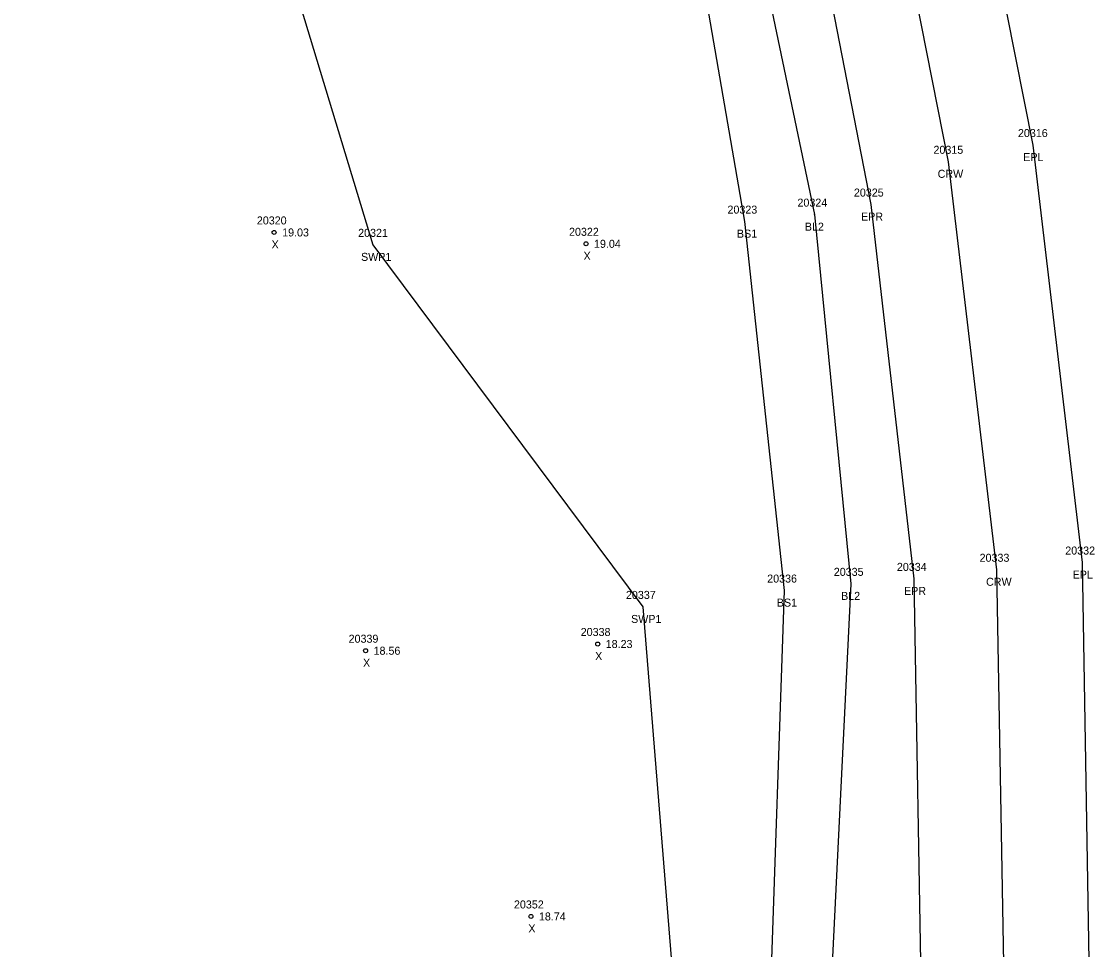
# Model space of a CAD drawing. Extents: x 2432729 to 2433340, y 684958 to 688103.
# Drawn here: x 2433033 to 2433167, y 686221.7 to 686337.6 of the extents above; entities that cross this region are included whole.
import ezdxf

# ---------------------------------------------------------------- set-up
doc = ezdxf.new("R2010")
doc.units = 0
for name, color, linetype in [('RD_DTM_BkLn1', 7, 'Continuous'), ('RD_DTM_BkLn2', 7, 'Continuous'), ('RD_EX_H2O', 7, 'Continuous'), ('RD_EX_H2O_txCode', 7, 'Continuous'), ('RD_EX_Road', 7, 'Continuous'), ('RD_EX_Road_txCode', 7, 'Continuous'), ('RD_Sketch8', 7, 'Continuous'), ('RD_SMD_Locator', 7, 'Continuous'), ('RD_SMD_Misc', 7, 'Continuous')]:
    doc.layers.add(name, color=color, linetype=linetype)

msp = doc.modelspace()

# ---------------------------------------------------------------- linework, layer by layer
at = {"layer": 'RD_DTM_BkLn1'}
for points in [[(2432926.02, 687213.66), (2432924.35, 687158.94), (2432925.68, 687108.84), (2432939.7, 687000.92), (2432956.93, 686927.39), (2432975, 686866.8), (2433007.19, 686769.33), (2433041.66, 686669.67), (2433075.97, 686569.51), (2433108.49, 686474.01), (2433123.82, 686426.48), (2433137.99, 686374.7), (2433148.76, 686320.1), (2433154.8, 686269.16), (2433155.78, 686212.93), (2433152.37, 686164.52), (2433145.67, 686113.9), (2433140.38, 686078.83)], [(2432898.98, 687049.37), (2432906.9, 687044.55), (2432919.33, 686997.25), (2432938.84, 686920.72), (2432957.15, 686862.46), (2432990.45, 686763.71), (2433024.84, 686664.51), (2433058.68, 686562.8), (2433090.41, 686467.11), (2433107.21, 686420.87), (2433120.26, 686369.86), (2433132.05, 686313.5), (2433136.59, 686267.4), (2433133.92, 686213.17), (2433133.74, 686165.58), (2433125.69, 686115.89), (2433123.08, 686088.41), (2433128.09, 686081.14)]]:
    msp.add_lwpolyline(points, dxfattribs=at)
at = {"layer": 'RD_DTM_BkLn2'}
msp.add_lwpolyline([(2432916.74, 686973.9), (2432925.37, 686926.35), (2432950.18, 686859.06), (2432982.46, 686761.59), (2433017.67, 686659.38), (2433053.8, 686561.16), (2433080.54, 686460.75), (2433098.39, 686424.64), (2433113.62, 686368.79), (2433123.31, 686312.63), (2433128.29, 686266.56), (2433126.49, 686214.47), (2433123.88, 686164.31), (2433114.46, 686111.82), (2433110.48, 686084.68), (2433120.95, 686072.12)], dxfattribs=at)
at = {"layer": 'RD_EX_H2O'}
msp.add_lwpolyline([(2433059.53, 686447.22), (2433075.46, 686410.47), (2433059.4, 686367.42), (2433076.9, 686309.73), (2433110.63, 686264.52), (2433114.63, 686215.04), (2433113.03, 686166.79), (2433114.46, 686111.82), (2433110.48, 686084.68), (2433120.95, 686072.12)], dxfattribs=at)
at = {"layer": 'RD_EX_Road'}
for points in [[(2432915.64, 687215.4), (2432913.86, 687159.12), (2432915.08, 687107.55), (2432919.97, 687053.4), (2432928.7, 686998.89), (2432946.77, 686924.59), (2432964.57, 686864), (2432997.3, 686766.34), (2433031.44, 686666.38), (2433066.06, 686565.78), (2433098.73, 686469.74), (2433113.88, 686422.91), (2433127.93, 686372.14), (2433139.1, 686314.76), (2433144.47, 686268.02), (2433145.44, 686213), (2433142.32, 686164.92), (2433135.44, 686115.75), (2433128.09, 686081.14)], [(2433070.23, 686619.38), (2433072.02, 686607.31), (2433079.53, 686592.62), (2433082.99, 686582.32), (2433082.14, 686577.64), (2433086.96, 686563.7), (2433088.99, 686562.5), (2433099.45, 686534.09), (2433118.26, 686478), (2433133.83, 686430.29), (2433148.35, 686377.56), (2433159.33, 686322.19), (2433165.5, 686270.06), (2433166.43, 686212.82), (2433163.02, 686162.81), (2433156.19, 686111.14), (2433152.88, 686076.43)]]:
    msp.add_lwpolyline(points, dxfattribs=at)
at = {"layer": 'RD_SMD_Locator'}
for centre, radius in [((2433159.33, 686322.19), 0.001), ((2433148.76, 686320.1), 0.001), ((2433139.1, 686314.76), 0.001), ((2433132.05, 686313.5), 0.001), ((2433123.31, 686312.63), 0.001), ((2433064.57, 686311.28), 0.25), ((2433076.9, 686309.73), 0.001), ((2433103.52, 686309.86), 0.25), ((2433165.5, 686270.06), 0.001), ((2433144.47, 686268.02), 0.001), ((2433154.8, 686269.16), 0.001), ((2433128.29, 686266.56), 0.001), ((2433136.59, 686267.4), 0.001), ((2433110.63, 686264.52), 0.001), ((2433104.98, 686259.89), 0.25), ((2433075.99, 686259.05), 0.25), ((2433096.64, 686225.87), 0.25)]:
    msp.add_circle(centre, radius, dxfattribs=at)

# ---------------------------------------------------------------- texts
at = {"layer": 'RD_EX_H2O_txCode'}
for s, p in [('20321', (2433075.06, 686310.73)), ('SWP1', (2433075.42, 686307.73)), ('20337', (2433108.51, 686265.52)), ('SWP1', (2433109.15, 686262.52))]:
    msp.add_text(s, height=1, dxfattribs=at).set_placement(p)
at = {"layer": 'RD_EX_Road_txCode'}
for s, p in [('20316', (2433157.47, 686323.19)), ('EPL', (2433158.13, 686320.19)), ('20325', (2433136.98, 686315.76)), ('EPR', (2433137.87, 686312.76)), ('20332', (2433163.38, 686271.06)), ('20334', (2433142.35, 686269.02)), ('EPL', (2433164.3, 686268.06)), ('EPR', (2433143.24, 686266.02))]:
    msp.add_text(s, height=1, dxfattribs=at).set_placement(p)
at = {"layer": 'RD_Sketch8'}
for s, p in [('20320', (2433062.41, 686312.28)), ('19.03', (2433065.57, 686310.78)), ('20322', (2433101.4, 686310.86)), ('X', (2433064.25, 686309.28)), ('19.04', (2433104.52, 686309.36)), ('X', (2433103.21, 686307.86)), ('20338', (2433102.86, 686260.89)), ('20339', (2433073.87, 686260.05)), ('18.23', (2433105.98, 686259.39)), ('18.56', (2433076.99, 686258.55)), ('X', (2433104.66, 686257.89)), ('X', (2433075.67, 686257.05)), ('20352', (2433094.52, 686226.87)), ('18.74', (2433097.64, 686225.37)), ('X', (2433096.32, 686223.87))]:
    msp.add_text(s, height=1, dxfattribs=at).set_placement(p)
at = {"layer": 'RD_SMD_Misc'}
for s, p in [('20315', (2433146.92, 686321.1)), ('CRW', (2433147.44, 686318.1)), ('20324', (2433129.93, 686314.5)), ('20323', (2433121.19, 686313.63)), ('BL2', (2433130.85, 686311.5)), ('BS1', (2433122.37, 686310.63)), ('20333', (2433152.68, 686270.16)), ('20335', (2433134.47, 686268.4)), ('20336', (2433126.15, 686267.56)), ('CRW', (2433153.49, 686267.16)), ('BS1', (2433127.35, 686264.56)), ('BL2', (2433135.38, 686265.4))]:
    msp.add_text(s, height=1, dxfattribs=at).set_placement(p)

doc.saveas('drawing.dxf')
